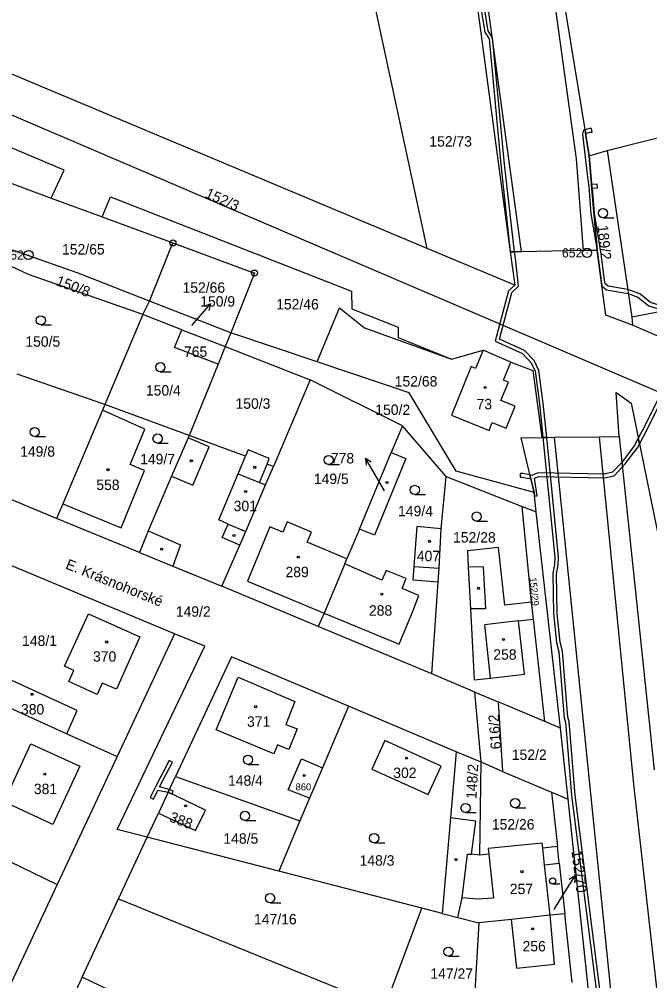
# Model space of a CAD drawing. Extents: x -783948 to -781889, y -1005870 to -1004430.
# Drawn here: x -783020.1 to -782917.3, y -1005140.8 to -1004983.9 of the extents above; entities that cross this region are included whole.
import ezdxf

# ---------------------------------------------------------------- set-up
doc = ezdxf.new("R2010")
doc.units = 0
for name, color, linetype in [('Vrstva 1', 7, 'Continuous'), ('Vrstva 13', 7, 'Continuous'), ('Vrstva 2', 7, 'Continuous'), ('Vrstva 3', 7, 'Continuous'), ('Vrstva 4', 7, 'Continuous'), ('Vrstva 5', 7, 'Continuous'), ('Vrstva 6', 7, 'Continuous'), ('Vrstva 7', 7, 'Continuous'), ('Vrstva 8', 7, 'Continuous')]:
    doc.layers.add(name, color=color, linetype=linetype)

msp = doc.modelspace()

# ---------------------------------------------------------------- linework, layer by layer
at = {"layer": 'Vrstva 1'}
for p, q in [((-782953.56, -1005021.28), (-783115.01, -1004953.5)), ((-782932.67, -1004972.37), (-782927.15, -1005006.15)), ((-782953.56, -1005021.28), (-782962.02, -1004982.04)), ((-782945.37, -1004982.08), (-782940.02, -1005021.84)), ((-782924.2, -1005005.29), (-782908.62, -1005001.3)), ((-782927.15, -1005006.15), (-782924.2, -1005005.29)), ((-782927.15, -1005006.15), (-782925.88, -1005021.59)), ((-782924.2, -1005005.29), (-782920.21, -1005032.48)), ((-783023.02, -1005010.02), (-783014.85, -1005013.04)), ((-783014.85, -1005013.04), (-783006.56, -1005016.1)), ((-783006.56, -1005016.1), (-782995.02, -1005020.37)), ((-782998.86, -1005029.87), (-782995.02, -1005020.37)), ((-782995.02, -1005020.37), (-782981.72, -1005025.29)), ((-782981.72, -1005025.29), (-782985.59, -1005035.06)), ((-782999.94, -1005032.04), (-782998.86, -1005029.87)), ((-782985.59, -1005035.06), (-782998.86, -1005029.87)), ((-782900.7, -1005028.79), (-782920.21, -1005032.48)), ((-782971.51, -1005039.79), (-782967.89, -1005030.95)), ((-782999.94, -1005032.04), (-783006.14, -1005046.74)), ((-782993.57, -1005034.53), (-782999.94, -1005032.04)), ((-782920.21, -1005032.48), (-782920.12, -1005033.77)), ((-782993.57, -1005034.53), (-782986.5, -1005037.29)), ((-782899.77, -1005042.67), (-782920.12, -1005033.77)), ((-782985.59, -1005035.06), (-782986.5, -1005037.29)), ((-782971.51, -1005039.79), (-782985.59, -1005035.06)), ((-782986.5, -1005037.29), (-782987.66, -1005040.14)), ((-782986.5, -1005037.29), (-782972.67, -1005042.7)), ((-782949.63, -1005039.35), (-782944.42, -1005037.87)), ((-782939.93, -1005039.81), (-782944.42, -1005037.87)), ((-782987.66, -1005040.14), (-782992.39, -1005051.79)), ((-782939.93, -1005039.81), (-782936.33, -1005041.21)), ((-783006.14, -1005046.74), (-783020.39, -1005041.77)), ((-782972.67, -1005042.7), (-782978.65, -1005056.84)), ((-782957.57, -1005050.22), (-782972.67, -1005042.7)), ((-782936.33, -1005041.21), (-782934.89, -1005052.11)), ((-783006.14, -1005046.74), (-783006.51, -1005047.67)), ((-782992.39, -1005051.79), (-783006.14, -1005046.74)), ((-783006.51, -1005047.67), (-783012.96, -1005062.93)), ((-782999.61, -1005050.78), (-783006.51, -1005047.67)), ((-782957.57, -1005050.22), (-782959.43, -1005054.57)), ((-782922.29, -1005051.97), (-782916.56, -1005106.32)), ((-782979.31, -1005055.56), (-782982.78, -1005054.12)), ((-782964.62, -1005067.05), (-782959.43, -1005054.57)), ((-782959.43, -1005054.57), (-782957.07, -1005055.53)), ((-782957.07, -1005055.53), (-782962.16, -1005068.05)), ((-783013.98, -1005065.35), (-783027.87, -1005059.51)), ((-782951.29, -1005067), (-782950.45, -1005058.48)), ((-782950.45, -1005058.48), (-782938.09, -1005063.35)), ((-782935.79, -1005064.26), (-782936.14, -1005061.11)), ((-783012.96, -1005062.93), (-783013.98, -1005065.35)), ((-783012.96, -1005062.93), (-783003.45, -1005066.86)), ((-782938.09, -1005063.35), (-782935.79, -1005064.26)), ((-782936.55, -1005079.01), (-782938.09, -1005063.35)), ((-782931.85, -1005099.54), (-782935.79, -1005064.26)), ((-783000.45, -1005070.86), (-783013.98, -1005065.35)), ((-782964.62, -1005067.05), (-782966.68, -1005071.9)), ((-782962.16, -1005068.05), (-782964.62, -1005067.05)), ((-782951.29, -1005067), (-782955.25, -1005066.65)), ((-782951.64, -1005073.46), (-782951.29, -1005067)), ((-782966.68, -1005071.9), (-782973.12, -1005069.2)), ((-782967.02, -1005072.72), (-782966.68, -1005071.9)), ((-782994.76, -1005084.16), (-783021.91, -1005072.77)), ((-782967.02, -1005072.72), (-782970.39, -1005080.77)), ((-782960.94, -1005075.4), (-782967.02, -1005072.72)), ((-782951.79, -1005075.65), (-782951.64, -1005073.46)), ((-782982.85, -1005075.57), (-782970.39, -1005080.77)), ((-782952.82, -1005090.67), (-782951.79, -1005075.65)), ((-782971.34, -1005082.96), (-782987.02, -1005076.36)), ((-782936.24, -1005081.78), (-782936.55, -1005079.01)), ((-782970.39, -1005080.77), (-782971.34, -1005082.96)), ((-782934.38, -1005098.47), (-782936.24, -1005081.78)), ((-782952.82, -1005090.67), (-782971.34, -1005082.96)), ((-782994.76, -1005084.16), (-783004.12, -1005104.17)), ((-783010.64, -1005096.66), (-783022.7, -1005091.12)), ((-782945.78, -1005093.65), (-782952.82, -1005090.67)), ((-782945.78, -1005093.65), (-782942.02, -1005095.24)), ((-782944.78, -1005105.12), (-782945.78, -1005093.65)), ((-783024.44, -1005094.96), (-783012.33, -1005100.45)), ((-782966.41, -1005095.98), (-782970.66, -1005106.04)), ((-782948.82, -1005103.41), (-782966.41, -1005095.98)), ((-782934.38, -1005098.47), (-782942.02, -1005095.24)), ((-782942.02, -1005095.24), (-782941.29, -1005106.6)), ((-783012.33, -1005100.45), (-783010.64, -1005096.66)), ((-782931.85, -1005099.54), (-782934.38, -1005098.47)), ((-783012.33, -1005100.45), (-783004.12, -1005104.17)), ((-782930.61, -1005111.11), (-782931.85, -1005099.54)), ((-782948.82, -1005103.41), (-782949.77, -1005114.16)), ((-782944.78, -1005105.12), (-782948.82, -1005103.41)), ((-783004.12, -1005104.17), (-783013.87, -1005125.04)), ((-782944.99, -1005120.25), (-782944.78, -1005105.12)), ((-782941.29, -1005106.6), (-782944.78, -1005105.12)), ((-782970.66, -1005106.04), (-782972.74, -1005110.96)), ((-782941.29, -1005106.6), (-782933.28, -1005109.98)), ((-782995.82, -1005110), (-782994.6, -1005107.41)), ((-782994.6, -1005107.41), (-782974.31, -1005114.68)), ((-782995.82, -1005110), (-782997.38, -1005113.39)), ((-782989.73, -1005112.9), (-782995.82, -1005110)), ((-782933.28, -1005109.98), (-782930.61, -1005111.11)), ((-782933.28, -1005109.98), (-782932.32, -1005118.88)), ((-783044.29, -1005110.32), (-783013.87, -1005125.04)), ((-782972.74, -1005110.96), (-782974.31, -1005114.68)), ((-782914.35, -1005262.66), (-782930.61, -1005111.11)), ((-782991.34, -1005116.27), (-782989.73, -1005112.9)), ((-782999.22, -1005117.35), (-782997.38, -1005113.39)), ((-782997.38, -1005113.39), (-782991.34, -1005116.27)), ((-782974.31, -1005114.68), (-782977.78, -1005122.9)), ((-782949.77, -1005114.16), (-782951.14, -1005129.78)), ((-782945.66, -1005114.7), (-782949.77, -1005114.16)), ((-782946.36, -1005120.13), (-782945.66, -1005114.7)), ((-783003.87, -1005127.37), (-782999.22, -1005117.35)), ((-782977.78, -1005122.9), (-782999.22, -1005117.35)), ((-782934.81, -1005118.29), (-782943.63, -1005119.2)), ((-782932.03, -1005121.6), (-782932.32, -1005118.88)), ((-782944.99, -1005120.25), (-782946.36, -1005120.13)), ((-782932.03, -1005121.6), (-782931.14, -1005129.82)), ((-782954.45, -1005128.93), (-782977.78, -1005122.9)), ((-783013.87, -1005125.04), (-783023.28, -1005145.16)), ((-783009.84, -1005140.2), (-783003.87, -1005127.37)), ((-783003.87, -1005127.37), (-782960.46, -1005145.08)), ((-782960.46, -1005145.08), (-782954.45, -1005128.93)), ((-782951.14, -1005129.78), (-782954.45, -1005128.93)), ((-782931.14, -1005129.82), (-782933.54, -1005130.08)), ((-782929.92, -1005141.06), (-782931.14, -1005129.82)), ((-782945.15, -1005131.33), (-782946.27, -1005150.87)), ((-783009.84, -1005140.2), (-783017.65, -1005157)), ((-782947.58, -1005169.77), (-783009.84, -1005140.2))]:
    msp.add_line(p, q, dxfattribs=at)
for points in [[(-783014.85, -1005013.04), (-783012.76, -1005008.51), (-783056.45, -1004989.98)], [(-783006.56, -1005016.1), (-783005.19, -1005012.86), (-782965.9, -1005028.22), (-782965.86, -1005031.14), (-782958.32, -1005034.09), (-782958.3, -1005035.81), (-782949.63, -1005039.35)], [(-782998.86, -1005029.87), (-783010.46, -1005025.33), (-783026.93, -1005019.54)], [(-782999.94, -1005032.04), (-783018.56, -1005025.52), (-783027.65, -1005021.28)], [(-782940.02, -1005021.84), (-782939.29, -1005027.27), (-782953.56, -1005021.28)], [(-782925.88, -1005021.59), (-782928.16, -1005021.63), (-782938.18, -1005021.81), (-782940.02, -1005021.84)], [(-782920.12, -1005033.77), (-782924.46, -1005032.18), (-782925.88, -1005021.59)], [(-782967.89, -1005030.95), (-782963.79, -1005034.24), (-782949.63, -1005039.35)], [(-782987.66, -1005040.14), (-782994.76, -1005037.43), (-782993.57, -1005034.53)], [(-782944.42, -1005037.87), (-782945.71, -1005040.85), (-782946.4, -1005040.51)], [(-782936.14, -1005061.11), (-782948.86, -1005057.63), (-782956.51, -1005044.83), (-782971.51, -1005039.79)], [(-782946.4, -1005040.51), (-782949.63, -1005048.48), (-782943.48, -1005050.96)], [(-782943.48, -1005050.96), (-782942.96, -1005049.67), (-782940.7, -1005050.58), (-782939.25, -1005046.99), (-782941.54, -1005046.07), (-782940.33, -1005043.07), (-782941.12, -1005042.76), (-782939.93, -1005039.81)], [(-782922.29, -1005051.97), (-782922.75, -1005044.77), (-782920.33, -1005046.49), (-782913.56, -1005079.53)], [(-782950.45, -1005058.48), (-782950.85, -1005058.06), (-782957.57, -1005050.22)], [(-783003.45, -1005066.86), (-782999.67, -1005057.49), (-783001.99, -1005056.54), (-782999.61, -1005050.78)], [(-782992.39, -1005051.79), (-782992.55, -1005052.17), (-782995.23, -1005058.41), (-782999.06, -1005067.34), (-783000.45, -1005070.86)], [(-782982.78, -1005054.12), (-782983.21, -1005055.16), (-782992.39, -1005051.79)], [(-782936.14, -1005061.11), (-782938.26, -1005052.15), (-782934.89, -1005052.11)], [(-782934.89, -1005052.11), (-782932.86, -1005052.09), (-782925.51, -1005052.01), (-782922.29, -1005051.97)], [(-782978.65, -1005056.84), (-782979.68, -1005056.46), (-782979.31, -1005055.56)], [(-782987.02, -1005076.36), (-782984.09, -1005069.7), (-782983.13, -1005067.44), (-782979.92, -1005059.85), (-782978.65, -1005056.84)], [(-782973.12, -1005069.2), (-782972.43, -1005067.55), (-782976.38, -1005065.9), (-782977.08, -1005067.58), (-782979.23, -1005066.68), (-782982.85, -1005075.57)], [(-782955.25, -1005066.65), (-782955.76, -1005073.17), (-782955.93, -1005075.36), (-782951.79, -1005075.65)], [(-783000.45, -1005070.86), (-782995.02, -1005073.1), (-782987.02, -1005076.36)], [(-782936.55, -1005079.01), (-782940.89, -1005079.49), (-782941.94, -1005070.06), (-782947.02, -1005070.63), (-782946.88, -1005073.27), (-782946.51, -1005080.1), (-782945.89, -1005091.67), (-782943.22, -1005091.37), (-782937.71, -1005090.76), (-782938.68, -1005082.05), (-782936.24, -1005081.78)], [(-782954.94, -1005077.92), (-782957.67, -1005076.74), (-782956.99, -1005075.15), (-782960.27, -1005073.8), (-782960.94, -1005075.4)], [(-782970.39, -1005080.77), (-782958.13, -1005085.84), (-782955.85, -1005080.35), (-782954.94, -1005077.92)], [(-783004.23, -1005093.2), (-783006.53, -1005092.2), (-783007.35, -1005094.03), (-783011.98, -1005091.94), (-783011.16, -1005090.11), (-783012.69, -1005089.44), (-783008.76, -1005080.91), (-783000.42, -1005084.65), (-783004.23, -1005093.2)], [(-782999.22, -1005117.35), (-783004.1, -1005116.09), (-782989.84, -1005086.15), (-782994.76, -1005084.16)], [(-782966.41, -1005095.98), (-782985.47, -1005087.93), (-782994.6, -1005107.41)], [(-782984.37, -1005091.2), (-782975.12, -1005095.2), (-782976.59, -1005098.92), (-782974.78, -1005099.68), (-782976.14, -1005103.03), (-782977.95, -1005102.28), (-782978.55, -1005103.71), (-782987.96, -1005099.8), (-782984.37, -1005091.2)], [(-783018.2, -1005102.12), (-783010.19, -1005105.74), (-783014.61, -1005115.24), (-783022.55, -1005111.59), (-783018.2, -1005102.12)], [(-782953.4, -1005110.35), (-782951.31, -1005105.72), (-782960.48, -1005101.58), (-782962.57, -1005106.21), (-782953.4, -1005110.35)], [(-782972.74, -1005110.96), (-782976.24, -1005109.61), (-782974.08, -1005104.56), (-782970.66, -1005106.04)], [(-782943.63, -1005119.2), (-782943.54, -1005120.09), (-782944.99, -1005120.25)], [(-782932.32, -1005118.88), (-782934.72, -1005119.14), (-782934.81, -1005118.29)], [(-782933.54, -1005130.08), (-782934.43, -1005121.86), (-782932.03, -1005121.6)], [(-782951.14, -1005129.78), (-782948.55, -1005130.45), (-782945.15, -1005131.33)], [(-782933.54, -1005130.08), (-782939.84, -1005130.76), (-782945.15, -1005131.33)]]:
    msp.add_lwpolyline(points, dxfattribs=at)
at = {"layer": 'Vrstva 13'}
for points in [[(-782944.37, -1004981.04), (-782945.6, -1004980.38), (-782946.58, -1004979.86), (-782948.8, -1004979.67), (-782948.77, -1004980.28), (-782946.76, -1004980.44), (-782945.5, -1004981.11), (-782944.91, -1004981.42), (-782944.19, -1004985.99), (-782943.48, -1004987.08), (-782941.58, -1005007.59), (-782940.02, -1005021.84), (-782939.31, -1005021.83), (-782940.98, -1005007.53), (-782942.9, -1004986.88), (-782943.61, -1004985.77)], [(-782925.88, -1005021.59), (-782926.76, -1005010.84), (-782927.15, -1005006.15), (-782927.69, -1005002.86), (-782927.84, -1005001.9), (-782928.07, -1005001.96), (-782928.25, -1005002.64), (-782927.43, -1005009.66), (-782927.24, -1005011.18), (-782926.87, -1005015.61)], [(-782927.84, -1005001.9), (-782927.69, -1005002.86), (-782927.58, -1005002.45), (-782927.04, -1005002.3), (-782926.69, -1005002.29), (-782926.78, -1005001.69), (-782927.13, -1005001.71)], [(-782914.81, -1005031.46), (-782913.6, -1005031.23), (-782913.86, -1005031.12), (-782917.17, -1005030.11), (-782918.92, -1005028.68), (-782920.87, -1005027.98), (-782924.06, -1005027.45), (-782924.57, -1005027.04), (-782924.67, -1005026.43), (-782925.23, -1005022.23), (-782926.27, -1005015.54), (-782926.61, -1005011.43), (-782925.81, -1005011.38), (-782925.86, -1005010.78), (-782926.76, -1005010.84), (-782925.88, -1005021.59), (-782925.1, -1005027.38), (-782924.32, -1005028.01), (-782920.78, -1005028.62), (-782919.22, -1005029.2), (-782917.46, -1005030.65)], [(-782940.02, -1005021.84), (-782939.29, -1005027.27), (-782940.33, -1005028.2), (-782942.46, -1005036.39), (-782938.04, -1005038.43), (-782936.61, -1005039.91), (-782935.96, -1005041.32), (-782935.24, -1005046.58), (-782934.7, -1005052.11), (-782934.09, -1005052.1), (-782934.64, -1005046.5), (-782935.38, -1005041.16), (-782936.11, -1005039.57), (-782937.68, -1005037.93), (-782941.76, -1005036.05), (-782939.79, -1005028.48), (-782938.7, -1005027.41), (-782939.13, -1005023.32), (-782939.31, -1005021.83)], [(-782919.15, -1005052.25), (-782918.96, -1005053.18), (-782917.69, -1005050.8), (-782911.18, -1005037.68), (-782908.96, -1005033.22), (-782913.6, -1005031.23), (-782914.81, -1005031.46), (-782914.06, -1005031.69), (-782909.78, -1005033.52), (-782911.73, -1005037.44), (-782918.23, -1005050.53)], [(-782935.39, -1005058.48), (-782924.64, -1005058.69), (-782923.08, -1005058.35), (-782921.76, -1005056.96), (-782921.27, -1005056.43), (-782919.29, -1005053.79), (-782918.96, -1005053.18), (-782919.15, -1005052.25), (-782919.8, -1005053.47), (-782921.73, -1005056.05), (-782921.85, -1005056.17), (-782923.38, -1005057.8), (-782924.7, -1005058.09), (-782935.51, -1005057.88), (-782936.49, -1005058.3), (-782936.82, -1005058.23), (-782936.67, -1005058.87), (-782936.14, -1005061.11), (-782936.08, -1005061.69), (-782935.63, -1005061.63), (-782936.09, -1005058.78)], [(-782936.67, -1005058.87), (-782936.82, -1005058.23), (-782938.03, -1005058), (-782938.43, -1005058.01), (-782938.4, -1005058.61), (-782938.07, -1005058.6)], [(-782995.62, -1005109.58), (-782997.22, -1005109.13), (-782995.09, -1005105.11), (-782995.63, -1005104.83), (-782997.88, -1005109.11), (-782998.72, -1005110.85), (-782998.18, -1005111.11), (-782997.46, -1005109.68), (-782995.82, -1005110)], [(-782995.82, -1005110), (-782995.17, -1005110.31), (-782994.96, -1005109.83), (-782995.36, -1005109.65), (-782995.62, -1005109.58)]]:
    msp.add_lwpolyline(points, close=True, dxfattribs=at)
msp.add_lwpolyline([(-782925.23, -1005143.83), (-782929.45, -1005110.46), (-782930.41, -1005098.47), (-782930.64, -1005097.77), (-782931.49, -1005086.97), (-782931.87, -1005085.5), (-782932.36, -1005080.81), (-782932.48, -1005074.36), (-782932.21, -1005072.92), (-782932.18, -1005071.65), (-782934.09, -1005052.1), (-782934.7, -1005052.11), (-782932.78, -1005071.67), (-782932.81, -1005072.86), (-782933.08, -1005074.32), (-782932.96, -1005080.85), (-782932.47, -1005085.6), (-782932.09, -1005087.07), (-782931.24, -1005097.89), (-782931.01, -1005098.59), (-782930.05, -1005110.52), (-782925.83, -1005143.89)], dxfattribs=at)
at = {"layer": 'Vrstva 3'}
for p, q in [((-782924.9, -1005016.27), (-782923.15, -1005016.27)), ((-783016.55, -1005033.76), (-783014.8, -1005033.76)), ((-782997.08, -1005041.39), (-782995.33, -1005041.39)), ((-783017.55, -1005051.96), (-783015.8, -1005051.96)), ((-782997.52, -1005053.04), (-782995.77, -1005053.04)), ((-782969.63, -1005056.53), (-782967.88, -1005056.53)), ((-782955.59, -1005061.42), (-782953.84, -1005061.42)), ((-782945.51, -1005065.77), (-782943.76, -1005065.77)), ((-782982.77, -1005105.45), (-782981.02, -1005105.45)), ((-782939.23, -1005112.54), (-782937.48, -1005112.54)), ((-782983.27, -1005114.61), (-782981.52, -1005114.61)), ((-782947.31, -1005113.33), (-782945.56, -1005113.33)), ((-782962.22, -1005118.25), (-782960.47, -1005118.25)), ((-782933.09, -1005124.97), (-782931.92, -1005124.97)), ((-782979.18, -1005128.04), (-782977.43, -1005128.04)), ((-782950.11, -1005136.76), (-782948.36, -1005136.76))]:
    msp.add_line(p, q, dxfattribs=at)
for centre, radius in [((-782924.9, -1005015.52), 0.75), ((-783016.55, -1005033.01), 0.75), ((-782997.08, -1005040.64), 0.75), ((-783017.55, -1005051.21), 0.75), ((-782997.52, -1005052.29), 0.75), ((-782969.63, -1005055.78), 0.75), ((-782955.59, -1005060.67), 0.75), ((-782945.51, -1005065.02), 0.75), ((-782982.77, -1005104.7), 0.75), ((-782939.23, -1005111.79), 0.75), ((-782983.27, -1005113.86), 0.75), ((-782947.31, -1005112.58), 0.75), ((-782962.22, -1005117.5), 0.75), ((-782933.1, -1005124.47), 0.502), ((-782979.18, -1005127.29), 0.75), ((-782950.11, -1005136.01), 0.75)]:
    msp.add_circle(centre, radius, dxfattribs=at)
at = {"layer": 'Vrstva 4'}
for p, q in [((-782938.18, -1005021.81), (-782948.3, -1004947.37)), ((-782936.21, -1004956.75), (-782929.27, -1005006.66)), ((-782929.27, -1005006.66), (-782928.16, -1005021.63)), ((-782932.86, -1005052.09), (-782921.8, -1005160.42)), ((-782925.51, -1005052.01), (-782919.91, -1005108.66)), ((-782989.12, -1005053.62), (-782992.55, -1005052.17)), ((-782991.77, -1005059.89), (-782989.12, -1005053.62)), ((-782984.41, -1005058.06), (-782983.21, -1005055.16)), ((-782980.93, -1005059.45), (-782979.68, -1005056.46)), ((-782987.52, -1005065.57), (-782984.41, -1005058.06)), ((-782984.41, -1005058.06), (-782980.93, -1005059.45)), ((-782995.23, -1005058.41), (-782991.77, -1005059.89)), ((-782980.93, -1005059.45), (-782979.92, -1005059.85)), ((-782986.03, -1005066.28), (-782987.52, -1005065.57)), ((-782999.06, -1005067.34), (-782993.76, -1005069.62)), ((-782986.97, -1005068.44), (-782986.03, -1005066.28)), ((-782986.03, -1005066.28), (-782983.13, -1005067.44)), ((-782984.09, -1005069.7), (-782986.97, -1005068.44)), ((-782993.76, -1005069.62), (-782995.02, -1005073.1)), ((-782955.76, -1005073.17), (-782951.64, -1005073.46)), ((-782944.42, -1005073.23), (-782946.88, -1005073.27)), ((-782944.42, -1005073.23), (-782944.05, -1005080.06)), ((-782944.05, -1005080.06), (-782946.51, -1005080.1)), ((-782941.99, -1005082.42), (-782944.19, -1005082.66)), ((-782943.22, -1005091.37), (-782944.19, -1005082.66)), ((-782938.68, -1005082.05), (-782941.99, -1005082.42)), ((-782919.91, -1005108.66), (-782904.65, -1005244.68)), ((-782934.43, -1005121.86), (-782934.72, -1005119.14)), ((-782947.89, -1005127.23), (-782947.01, -1005120.08)), ((-782947.01, -1005120.08), (-782946.36, -1005120.13)), ((-782943.54, -1005120.09), (-782942.78, -1005127.29)), ((-782948.55, -1005130.45), (-782947.89, -1005127.23)), ((-782945.43, -1005127.44), (-782947.89, -1005127.23)), ((-782942.78, -1005127.29), (-782945.43, -1005127.44)), ((-782932.79, -1005138.05), (-782933.54, -1005130.08)), ((-782938.98, -1005138.72), (-782939.84, -1005130.76)), ((-782938.98, -1005138.72), (-782932.79, -1005138.05))]:
    msp.add_line(p, q, dxfattribs=at)
at = {"layer": 'Vrstva 5'}
for centre in [(-782944.12, -1005043.97), (-782992.02, -1005055.91), (-782981.68, -1005056.99), (-783005.59, -1005057.38), (-782960.12, -1005059.47), (-782983.15, -1005060.93), (-782985.07, -1005068.1), (-782953.18, -1005069.07), (-782996.87, -1005070.34), (-782974.58, -1005071.65), (-782945.21, -1005076.72), (-782960.97, -1005077.69), (-782941.12, -1005085.07), (-783005.81, -1005085.49), (-783017.98, -1005094.01), (-782981.52, -1005096.03), (-782956.93, -1005104.45), (-783015.91, -1005107.05), (-782973.62, -1005107.27), (-782992.95, -1005112.23), (-782948.87, -1005120.99), (-782938.12, -1005122.96), (-782936.36, -1005132.29)]:
    msp.add_circle(centre, 0.175, dxfattribs=at)
at = {"layer": 'Vrstva 6'}
msp.add_line((-783060.19, -1004982.81), (-782841.72, -1005076.44), dxfattribs=at)
at = {"layer": 'Vrstva 7'}
for p, q in [((-782990.84, -1005032.57), (-782988.87, -1005030.31)), ((-782988.87, -1005030.31), (-782989.91, -1005030.73)), ((-782988.87, -1005030.31), (-782989.15, -1005031.39)), ((-782991.95, -1005033.85), (-782990.84, -1005032.57)), ((-782962.11, -1005058.09), (-782963.61, -1005055.49)), ((-782963.61, -1005055.49), (-782962.68, -1005056.11)), ((-782963.61, -1005055.49), (-782963.54, -1005056.61)), ((-782960.52, -1005060.82), (-782962.11, -1005058.09)), ((-782931.05, -1005126.2), (-782929.46, -1005123.66)), ((-782929.46, -1005123.66), (-782930.42, -1005124.24)), ((-782929.46, -1005123.66), (-782929.57, -1005124.77)), ((-782932.86, -1005129.12), (-782931.05, -1005126.2))]:
    msp.add_line(p, q, dxfattribs=at)
at = {"layer": 'Vrstva 8'}
for centre, radius in [((-782995.02, -1005020.37), 0.5), ((-782995.02, -1005020.37), 0.0303), ((-783018.57, -1005022.35), 0.75), ((-783018.57, -1005022.35), 0.03), ((-782927.51, -1005021.99), 0.75), ((-782927.51, -1005021.99), 0.03), ((-782981.72, -1005025.29), 0.5), ((-782981.72, -1005025.29), 0.0303)]:
    msp.add_circle(centre, radius, dxfattribs=at)

# ---------------------------------------------------------------- texts
at = {"layer": 'Vrstva 2'}
for s, height, p in [('152/73', 1.7, (-782953.22, -1005004.65)), ('152/65', 1.7, (-783013.1, -1005022.26)), ('152/66', 1.7, (-782993.46, -1005028.5)), ('150/9', 1.7, (-782990.57, -1005030.76)), ('152/46', 1.7, (-782978.19, -1005031.23)), ('150/5', 1.7, (-783019.08, -1005037.31)), ('765', 1.7, (-782993.22, -1005038.96)), ('152/68', 1.7, (-782958.86, -1005043.8)), ('150/4', 1.7, (-782999.43, -1005045.28)), ('150/3', 1.7, (-782984.82, -1005047.43)), ('73', 1.7, (-782945.52, -1005047.51)), ('150/2', 1.7, (-782962.03, -1005048.44)), ('149/8', 1.7, (-783019.93, -1005055.25)), ('149/7', 1.7, (-783000.37, -1005056.49)), ('778', 1.7, (-782969.27, -1005056.35)), ('149/5', 1.7, (-782972.05, -1005059.71)), ('558', 1.7, (-783007.51, -1005060.69)), ('301', 1.7, (-782985.12, -1005064.14)), ('149/4', 1.7, (-782958.32, -1005064.97)), ('152/28', 1.7, (-782949.35, -1005069.26)), ('407', 1.7, (-782955.26, -1005072.3)), ('289', 1.7, (-782976.67, -1005074.91)), ('149/2', 1.7, (-782994.55, -1005081.36)), ('288', 1.7, (-782963.06, -1005081.19)), ('148/1', 1.7, (-783019.61, -1005086.13)), ('370', 1.7, (-783008.05, -1005088.7)), ('258', 1.7, (-782942.79, -1005088.38)), ('380', 1.7, (-783019.79, -1005097.32)), ('371', 1.7, (-782982.94, -1005099.32)), ('152/2', 1.7, (-782939.78, -1005104.73)), ('302', 1.7, (-782959.1, -1005107.68)), ('381', 1.7, (-783017.69, -1005110.31)), ('148/4', 1.7, (-782986.04, -1005108.94)), ('860', 1.139, (-782975.02, -1005109.7)), ('152/26', 1.7, (-782943.03, -1005116.09)), ('148/5', 1.7, (-782986.79, -1005118.4)), ('148/3', 1.7, (-782964.59, -1005121.98)), ('257', 1.7, (-782940.1, -1005126.63)), ('147/16', 1.7, (-782981.8, -1005131.57)), ('256', 1.7, (-782938.02, -1005135.97)), ('147/27', 1.7, (-782953.05, -1005140.44))]:
    msp.add_text(s, height=height, dxfattribs=at).set_placement(p)
for s, height, rotation, p in [('152/3', 1.7, 336, (-782989.9, -1005012.88)), ('189/2', 1.7, 276, (-782925.81, -1005017.55)), ('150/8', 1.7, 339, (-783014.23, -1005027.21)), ('152/29', 1.14, 275, (-782936.88, -1005074.99)), ('616/2', 1.7, 94, (-782941.51, -1005102.93)), ('148/2', 1.7, 87, (-782945.53, -1005111.12)), ('388', 1.7, 339, (-782995.74, -1005114.71)), ('152/70', 1.7, 277, (-782930.05, -1005119.58))]:
    msp.add_text(s, height=height, rotation=rotation, dxfattribs=at).set_placement(p)
at = {"layer": 'Vrstva 7'}
msp.add_text('E. Krásnohorské', height=1.7, rotation=338, dxfattribs=at).set_placement((-783012.65, -1005073.46))
at = {"layer": 'Vrstva 8'}
for s, p in [('262', (-783022.67, -1005023.1)), ('652', (-782931.61, -1005022.74))]:
    msp.add_text(s, height=1.5, dxfattribs=at).set_placement(p)

doc.saveas('drawing.dxf')
